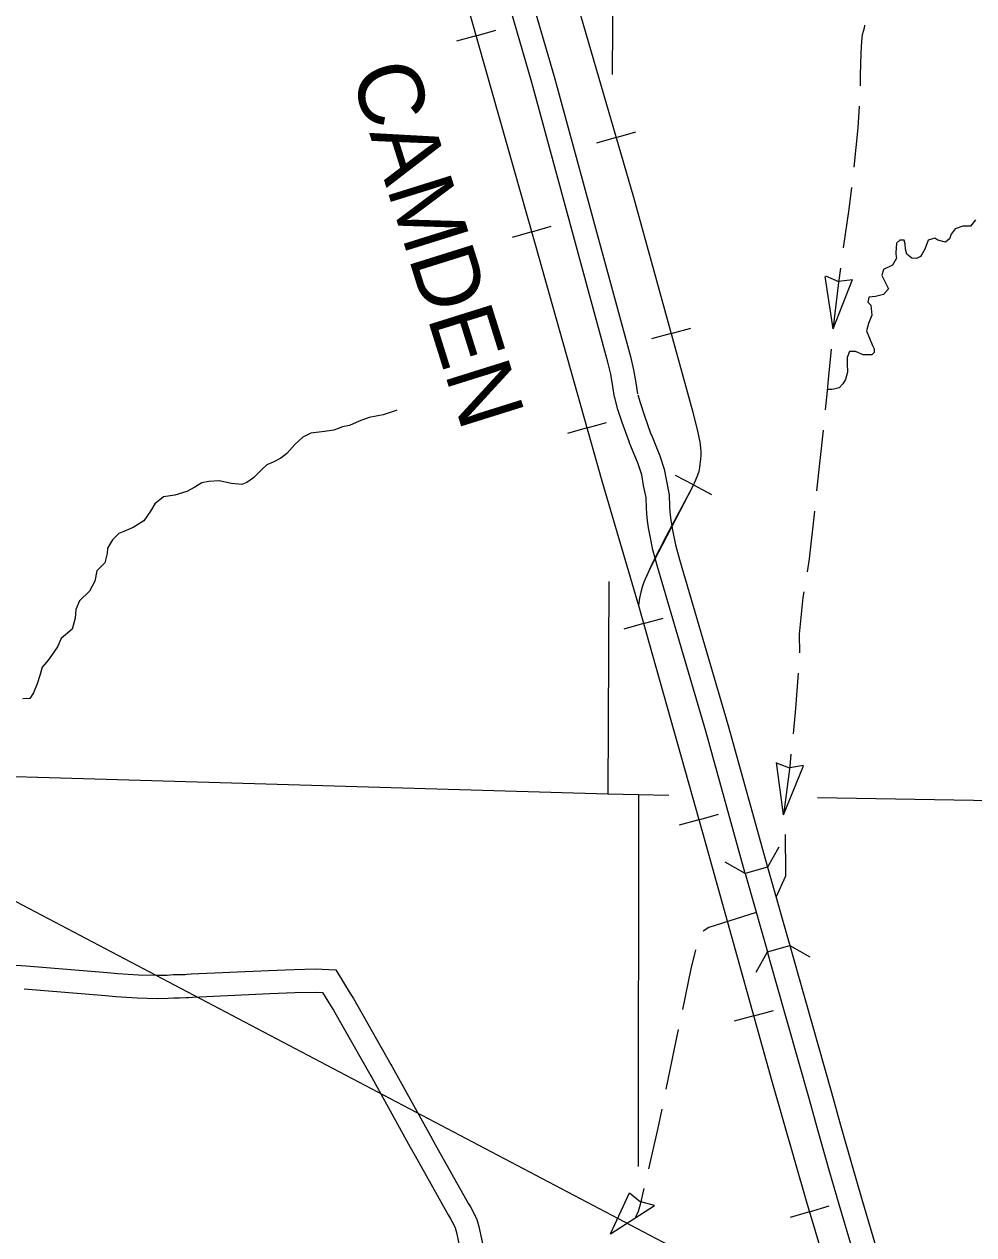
# Model space of a CAD drawing. Extents: x 1373094 to 1376427, y 1168361 to 1170494.
# Drawn here: x 1373700 to 1373802.5, y 1170123.5 to 1170254.2 of the extents above; entities that cross this region are included whole.
import ezdxf

# ---------------------------------------------------------------- set-up
doc = ezdxf.new("R2010")
doc.units = 0
doc.layers.add('R_Axis', color=7, linetype='Continuous')
doc.layers.add('R_Draft', color=7, linetype='Continuous')

msp = doc.modelspace()

# ---------------------------------------------------------------- linework, layer by layer
at = {"layer": 'R_Axis'}
for p, q in [((1373748.78, 1170252.98), (1373746.66, 1170252.38)), ((1373748.78, 1170252.98), (1373750.9, 1170253.58)), ((1373763.9, 1170242.01), (1373766.02, 1170242.62)), ((1373763.9, 1170242.01), (1373761.79, 1170241.39)), ((1373754.79, 1170231.81), (1373756.9, 1170232.41)), ((1373754.79, 1170231.81), (1373752.67, 1170231.21)), ((1373787.32, 1170221.34), (1373786.48, 1170227)), ((1373786.5, 1170227.04), (1373787.9, 1170226.44)), ((1373787.32, 1170221.34), (1373789.42, 1170226.67)), ((1373789.43, 1170226.63), (1373787.92, 1170226.44)), ((1373769.85, 1170220.82), (1373767.73, 1170220.24)), ((1373769.85, 1170220.82), (1373771.97, 1170221.41)), ((1373760.76, 1170210.64), (1373762.88, 1170211.23)), ((1373760.76, 1170210.64), (1373758.64, 1170210.04)), ((1373772.24, 1170204.48), (1373770.3, 1170205.51)), ((1373772.24, 1170204.48), (1373774.19, 1170203.45)), ((1373766.86, 1170189.5), (1373768.98, 1170190.1)), ((1373766.86, 1170189.5), (1373764.74, 1170188.9)), ((1373781.19, 1170174.48), (1373782.62, 1170173.93)), ((1373781.99, 1170168.84), (1373781.2, 1170174.51)), ((1373781.99, 1170168.84), (1373784.14, 1170174.14)), ((1373784.14, 1170174.17), (1373782.64, 1170173.93)), ((1373772.82, 1170168.32), (1373770.7, 1170167.73)), ((1373772.82, 1170168.32), (1373774.94, 1170168.92)), ((1373780.24, 1170163.18), (1373777.84, 1170162.5)), ((1373778.76, 1170147.14), (1373776.64, 1170146.55)), ((1373778.76, 1170147.14), (1373780.88, 1170147.73)), ((1373763.3, 1170123.59), (1373765.36, 1170128.01)), ((1373765.36, 1170128.01), (1373766.55, 1170127.06)), ((1373763.3, 1170123.59), (1373768.05, 1170126.67)), ((1373768.05, 1170126.67), (1373766.57, 1170127.04)), ((1373784.79, 1170125.98), (1373786.9, 1170126.61)), ((1373784.79, 1170125.98), (1373782.68, 1170125.35))]:
    msp.add_line(p, q, dxfattribs=at)
for points in [[(1373763.73, 1170213.95), (1373763.55, 1170215.1), (1373763.32, 1170216.42), (1373763.02, 1170217.72), (1373754.81, 1170247.92), (1373751.23, 1170260.23), (1373743.92, 1170286.2), (1373738.23, 1170305.76), (1373731.62, 1170327.55)], [(1373741.39, 1170303.85), (1373746.32, 1170286.89), (1373753.63, 1170260.92), (1373757.22, 1170248.6), (1373765.44, 1170218.33), (1373765.77, 1170216.92), (1373766.02, 1170215.5), (1373766.2, 1170214.33)], [(1373735.86, 1170298.49), (1373755.13, 1170230.59), (1373762.37, 1170204.92), (1373766.31, 1170191.46), (1373773.21, 1170166.93), (1373780.73, 1170140.1), (1373784.43, 1170127.18)], [(1373735.86, 1170298.49), (1373755.13, 1170230.59), (1373762.37, 1170204.92), (1373766.31, 1170191.46), (1373773.21, 1170166.93), (1373780.73, 1170140.1), (1373784.43, 1170127.18), (1373790.37, 1170107.3)], [(1373763.58, 1170267.45), (1373763.53, 1170259.25), (1373763.47, 1170248.8)], [(1373757.4, 1170264.38), (1373765.78, 1170235.55), (1373772.19, 1170212.34), (1373772.73, 1170210.13), (1373772.84, 1170209.59), (1373772.93, 1170209.14), (1373772.97, 1170208.77), (1373773.02, 1170208.5), (1373773.03, 1170208.05), (1373773.04, 1170207.64), (1373773.01, 1170207.29), (1373772.91, 1170206.35), (1373772.82, 1170205.94), (1373772.7, 1170205.52), (1373772.48, 1170204.98), (1373772.15, 1170204.27), (1373769.31, 1170198.93), (1373767.79, 1170195.99), (1373766.91, 1170193.97), (1373766.72, 1170193.42), (1373766.58, 1170192.9), (1373766.44, 1170192.26), (1373766.31, 1170191.46)], [(1373757.4, 1170264.38), (1373765.78, 1170235.55), (1373772.19, 1170212.34), (1373772.73, 1170210.13), (1373772.84, 1170209.59), (1373772.93, 1170209.14), (1373772.97, 1170208.77), (1373773.02, 1170208.5), (1373773.03, 1170208.05), (1373773.04, 1170207.64), (1373773.01, 1170207.29), (1373772.91, 1170206.35), (1373772.82, 1170205.94), (1373772.7, 1170205.52), (1373772.48, 1170204.98), (1373772.15, 1170204.27), (1373767.55, 1170195.42)], [(1373790.72, 1170254.13), (1373790.68, 1170253.81), (1373790.47, 1170253.07), (1373790.38, 1170252.4), (1373790.31, 1170251.08), (1373790.26, 1170248.74), (1373790.25, 1170247.57)], [(1373790.14, 1170245.37), (1373789.99, 1170243.04), (1373789.58, 1170238.8)], [(1373789.32, 1170236.61), (1373789.01, 1170234.24), (1373788.42, 1170230.07)], [(1373802.72, 1170233.11), (1373802.15, 1170232.43), (1373801.32, 1170232.42), (1373800.51, 1170232.14), (1373800.09, 1170231.56), (1373799.89, 1170231.06), (1373799.45, 1170230.68), (1373798.63, 1170230.92), (1373798.33, 1170231.12), (1373797.6, 1170230.92), (1373797.22, 1170229.93), (1373796.94, 1170229.43), (1373796.78, 1170229.16), (1373796.35, 1170228.93), (1373795.84, 1170228.97), (1373795.3, 1170229.38), (1373795.14, 1170229.93), (1373795.11, 1170230.52), (1373795.01, 1170230.91), (1373794.54, 1170230.92), (1373794.18, 1170230.57), (1373794.11, 1170229.53), (1373794.12, 1170229.41), (1373794.17, 1170228.96), (1373793.74, 1170228.22), (1373792.76, 1170227.74), (1373792.59, 1170227.09), (1373793.31, 1170225.66), (1373792.78, 1170225.03), (1373791.9, 1170224.84), (1373791.18, 1170224.76), (1373791.08, 1170224.22), (1373791.39, 1170223.88)], [(1373788.11, 1170227.9), (1373787.9, 1170226.34), (1373787.34, 1170221.53), (1373787.33, 1170221.34)], [(1373791.39, 1170223.88), (1373791.5, 1170222.81), (1373791.16, 1170221.92), (1373790.94, 1170221.12), (1373791.57, 1170219.54), (1373791.78, 1170219.19), (1373791.77, 1170218.76), (1373791.5, 1170218.54), (1373790.56, 1170218.54), (1373789.73, 1170218.88), (1373789.1, 1170218.89), (1373788.86, 1170218.23), (1373788.84, 1170217.6), (1373788.89, 1170216.67)], [(1373787.12, 1170219.15), (1373786.81, 1170215.87)], [(1373788.89, 1170216.67), (1373788.66, 1170215.86), (1373788.37, 1170215.4), (1373787.99, 1170214.96), (1373787.39, 1170214.8), (1373787.18, 1170214.78), (1373786.88, 1170214.77), (1373786.71, 1170214.74)], [(1373786.81, 1170215.87), (1373786.7, 1170214.62), (1373786.48, 1170212.58)], [(1373765.34, 1170209.05), (1373764.55, 1170211.23), (1373764.1, 1170212.63), (1373763.71, 1170214.04)], [(1373766.23, 1170214.21), (1373766.49, 1170213.36), (1373766.92, 1170212.04), (1373767.66, 1170209.97)], [(1373740.22, 1170212.56), (1373740.05, 1170212.46), (1373738.76, 1170212.03), (1373737.23, 1170211.76), (1373736.14, 1170211.36), (1373735.13, 1170210.88), (1373734.34, 1170210.75), (1373733.43, 1170210.38), (1373732.4, 1170210.25), (1373730.95, 1170210.06), (1373730.06, 1170209.63), (1373729.21, 1170208.83), (1373728.36, 1170207.86), (1373727.69, 1170207.35), (1373726.88, 1170206.94), (1373726.17, 1170206.63), (1373725.61, 1170206.1), (1373724.76, 1170205.24), (1373724.04, 1170204.72), (1373723.49, 1170204.53), (1373722.39, 1170204.63), (1373721.04, 1170204.9), (1373719.94, 1170204.86), (1373719.16, 1170204.7), (1373718.42, 1170204.24), (1373717.55, 1170203.77), (1373716.24, 1170203.37), (1373715.03, 1170203.2), (1373714.08, 1170202.43), (1373713.63, 1170201.64), (1373712.9, 1170200.61), (1373711.74, 1170199.86), (1373710.75, 1170199.46), (1373710.21, 1170199.22), (1373709.54, 1170198.54), (1373708.99, 1170197.63), (1373708.96, 1170197.06), (1373708.71, 1170196.05), (1373707.85, 1170195.19), (1373707.63, 1170194.08), (1373707.05, 1170193.02), (1373705.95, 1170191.97), (1373705.57, 1170191.01), (1373705.5, 1170190.09), (1373705.16, 1170188.9), (1373703.99, 1170187.88), (1373703.57, 1170187), (1373702.7, 1170185.7), (1373702.41, 1170185.35), (1373701.93, 1170184.81), (1373701.66, 1170183.89), (1373701.4, 1170183), (1373701.01, 1170182.04), (1373700.59, 1170181.41), (1373699.86, 1170181.39)], [(1373767.67, 1170209.94), (1373768.62, 1170207.61), (1373769.1, 1170206.17), (1373769.33, 1170204.88), (1373769.62, 1170203.4), (1373769.67, 1170202.13)], [(1373786.24, 1170210.4), (1373785.54, 1170203.83)], [(1373767.17, 1170201.98), (1373767.13, 1170203.11), (1373766.87, 1170204.42), (1373766.67, 1170205.55), (1373766.28, 1170206.74), (1373765.32, 1170209.08)], [(1373777.84, 1170162.5), (1373773.58, 1170177.9), (1373768.32, 1170195.76), (1373767.88, 1170197.46), (1373767.58, 1170198.94), (1373767.41, 1170199.83), (1373767.29, 1170200.61), (1373767.21, 1170201.37), (1373767.17, 1170202)], [(1373769.67, 1170202.11), (1373769.71, 1170201.58), (1373769.77, 1170200.93), (1373769.88, 1170200.24), (1373770.03, 1170199.41), (1373770.32, 1170198.02), (1373770.73, 1170196.42), (1373775.98, 1170178.59), (1373780.24, 1170163.19)], [(1373785.31, 1170201.65), (1373784.76, 1170196.5), (1373784.52, 1170195.1)], [(1373767.55, 1170195.42), (1373766.91, 1170193.97), (1373766.72, 1170193.42), (1373766.58, 1170192.9), (1373766.44, 1170192.26), (1373766.31, 1170191.46)], [(1373763.13, 1170194.05), (1373762.99, 1170171.11)], [(1373784.16, 1170192.93), (1373784.06, 1170192.32), (1373783.68, 1170188.37), (1373783.69, 1170186.35)], [(1373783.56, 1170184.16), (1373783.28, 1170180.33), (1373783, 1170177.58)], [(1373782.77, 1170175.39), (1373782.64, 1170174.08), (1373781.99, 1170168.84)], [(1373658.73, 1170174.09), (1373675.5, 1170173.64), (1373679.24, 1170173.58), (1373762.99, 1170171.11), (1373766.32, 1170171.05), (1373769.59, 1170170.99)], [(1373766.32, 1170171.05), (1373766.29, 1170130.87)], [(1373785.65, 1170170.72), (1373827.71, 1170170)], [(1373782.15, 1170166.73), (1373782.15, 1170165.75), (1373782.19, 1170163.56)], [(1373781.46, 1170165.37), (1373780.24, 1170163.18)], [(1373777.84, 1170162.5), (1373775.66, 1170163.72)], [(1373780.24, 1170163.19), (1373780.59, 1170161.93), (1373782.64, 1170154.73)], [(1373782.19, 1170163.56), (1373782.19, 1170162.21), (1373781.16, 1170159.92)], [(1373777.84, 1170162.5), (1373778.19, 1170161.25), (1373780.23, 1170154.05)], [(1373779.02, 1170158.31), (1373773.9, 1170156.67), (1373773.29, 1170156.27)], [(1373772.48, 1170154.28), (1373771.98, 1170152.23), (1373771.06, 1170147.84)], [(1373779.01, 1170151.87), (1373780.23, 1170154.05)], [(1373780.23, 1170154.05), (1373782.64, 1170154.73)], [(1373788, 1170126.75), (1373786.98, 1170130.23), (1373785.71, 1170134.67), (1373784.73, 1170138.21), (1373781.17, 1170150.75), (1373780.23, 1170154.05)], [(1373782.64, 1170154.73), (1373784.82, 1170153.51)], [(1373782.64, 1170154.73), (1373783.58, 1170151.43), (1373787.14, 1170138.88), (1373788.11, 1170135.34), (1373789.38, 1170130.93), (1373790.4, 1170127.45)], [(1373691.37, 1170153), (1373699.67, 1170152.59), (1373700.2, 1170152.54)], [(1373700.2, 1170152.54), (1373708.97, 1170151.82)], [(1373726.38, 1170152.04), (1373729.13, 1170152.16), (1373731.42, 1170152.21), (1373733.63, 1170152.11), (1373735.2, 1170149.57)], [(1373708.97, 1170151.82), (1373710.1, 1170151.73), (1373712.32, 1170151.57), (1373714.36, 1170151.52), (1373715.41, 1170151.55), (1373716.07, 1170151.59), (1373716.72, 1170151.59), (1373717.36, 1170151.61), (1373717.57, 1170151.63)], [(1373717.57, 1170151.63), (1373718.02, 1170151.66), (1373726.38, 1170152.04)], [(1373699.99, 1170150.05), (1373708.76, 1170149.33)], [(1373726.5, 1170149.54), (1373729.21, 1170149.67), (1373731.39, 1170149.7), (1373732.2, 1170149.67), (1373733.07, 1170148.26)], [(1373735.2, 1170149.57), (1373735.53, 1170149.03), (1373739.59, 1170141.89)], [(1373708.76, 1170149.33), (1373709.9, 1170149.24), (1373712.2, 1170149.07), (1373714.37, 1170149.02), (1373715.54, 1170149.05), (1373716.14, 1170149.09), (1373716.76, 1170149.09), (1373717.49, 1170149.12), (1373717.73, 1170149.13)], [(1373717.73, 1170149.13), (1373718.16, 1170149.16), (1373726.5, 1170149.54)], [(1373733.07, 1170148.26), (1373733.38, 1170147.75), (1373737.42, 1170140.66)], [(1373770.61, 1170145.68), (1373769.27, 1170139.22)], [(1373739.59, 1170141.89), (1373739.7, 1170141.7), (1373743.86, 1170134.19)], [(1373737.42, 1170140.66), (1373737.52, 1170140.48), (1373741.67, 1170132.97)], [(1373768.82, 1170137.07), (1373768.36, 1170134.86), (1373767.39, 1170130.62)], [(1373743.86, 1170134.19), (1373744.38, 1170133.24), (1373747.97, 1170126.85), (1373748.16, 1170126.5)], [(1373741.67, 1170132.97), (1373742.2, 1170132.02), (1373745.78, 1170125.64), (1373745.97, 1170125.3)], [(1373766.9, 1170128.48), (1373766.5, 1170126.76), (1373766.29, 1170126.01), (1373766.01, 1170125.4)], [(1373790.4, 1170127.45), (1373798.21, 1170101.02)], [(1373748.16, 1170126.5), (1373748.57, 1170125.75), (1373748.85, 1170125.14), (1373749.09, 1170124.39), (1373749.31, 1170123.4), (1373749.48, 1170122.55), (1373749.56, 1170122.05), (1373749.88, 1170120.28), (1373750.24, 1170117.69), (1373750.25, 1170117.51)], [(1373784.43, 1170127.18), (1373790.37, 1170107.3), (1373790.91, 1170105.25), (1373795.57, 1170089.79), (1373795.81, 1170089), (1373796.14, 1170088.13), (1373796.33, 1170087.66), (1373796.87, 1170086.38), (1373797.01, 1170086.06), (1373797.28, 1170085.54), (1373797.46, 1170085.16), (1373798.07, 1170083.99), (1373798.25, 1170083.68), (1373798.67, 1170083), (1373798.94, 1170082.6), (1373799.26, 1170082.14), (1373799.57, 1170081.73), (1373800.07, 1170081.1), (1373800.45, 1170080.64), (1373801.48, 1170079.47), (1373801.76, 1170079.18), (1373802.08, 1170078.87), (1373802.87, 1170078.17)], [(1373795.6, 1170101.04), (1373788, 1170126.75)], [(1373745.97, 1170125.3), (1373746.34, 1170124.63), (1373746.51, 1170124.24), (1373746.68, 1170123.74), (1373746.86, 1170122.88), (1373747.02, 1170122.09), (1373747.1, 1170121.63), (1373747.41, 1170119.89), (1373747.75, 1170117.38), (1373747.77, 1170117.24)]]:
    msp.add_lwpolyline(points, dxfattribs=at)
at = {"layer": 'R_Draft'}
msp.add_line((1373526.32, 1170250.36), (1374006.35, 1169997.87), dxfattribs=at)

# ---------------------------------------------------------------- texts
at = {"layer": 'R_Axis'}
msp.add_text('CAMDEN', height=7.04, rotation=287.3963, dxfattribs=at).set_placement((1373735.2, 1170249))

doc.saveas('drawing.dxf')
